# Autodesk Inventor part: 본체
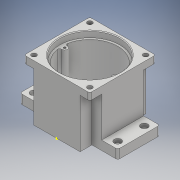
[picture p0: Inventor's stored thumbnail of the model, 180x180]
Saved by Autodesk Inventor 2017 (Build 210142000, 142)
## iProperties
Part Number: 본체
Material: 일반
Document SubType Name: Modeling
Designer: user
Density: 1 g/cm^3
Appearance: 기본값
Mass: 324.574 g
Surface Area: 793.93 cm^2
Volume: 324.574 cm^3
Author: user
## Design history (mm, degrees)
sketch "스케치1"
  geometry: L1 (-33, -47)-(33, -47); L2 (33, -47)-(33, 47); L3 (33, 47)-(-33, 47); L4 (-33, 47)-(-33, -47); L5 (-33, -47)-(33, 47); L6 (33, -47)-(-33, 47); L7 (-70, -30)-(70, -30); L8 (70, -30)-(70, 30); L9 (70, 30)-(-70, 30); L10 (-70, 30)-(-70, -30); L11 (-70, -30)-(70, 30); L12 (70, -30)-(-70, 30); 3 further points
  constraints: 24 end point, 5 midpoint, 4 parallel, 2 horizontal, 2 perpendicular, 1 coincident
  dimensions: "d3" = 60 distance of L7.end L8.end; "d4" = 66 distance of L2.end L3.end; "d5" = 37 distance between parallel lines of L10 L4; "d6" = 94 distance between parallel lines of L1 L3
extrude "돌출1" new body sketch "스케치1" distance "d7" = 13; taper "d8" = 0 deg
sketch "스케치2"
  geometry: L1 (33, -47)-(33, -30); L2 (33, -30)-(47, -30); L3 (47, -30)-(47, 30); L4 (47, 30)-(33, 30); L5 (33, 30)-(33, 47); L6 (33, 47)-(-33, 47); L7 (-33, 47)-(-33, 30); L8 (-33, 30)-(-47, 30); L9 (-47, 30)-(-47, -30); L10 (-47, -30)-(-33, -30); L11 (-33, -30)-(-33, -47); L12 (-33, -47)-(33, -47); 4 further points
  constraints: 24 end point, 8 perpendicular, 4 point on line, 3 coincident, 1 horizontal, 1 vertical
  dimensions: "d17" = 66 distance of L11.end L1.start; "d18" = 66 distance of L5.end L6.end; "d19" = 14 distance of L9.end L10.end; "d20" = 14 distance of L1.end L2.end; "d21" = 60 distance of L8.end L9.end; "d22" = 60 distance of L2.end L3.end
extrude "돌출2" join sketch "스케치2" distance "d11" = 57; taper "d12" = 0 deg
sketch "스케치4"
  geometry: L1 (47, 47)-(-47, 47); L2 (-47, 47)-(-47, -47); L3 (-47, -47)-(47, -47); L4 (47, -47)-(47, 47); L5 (47, 47)-(-47, -47); L6 (-47, 47)-(47, -47); 1 further point
  constraints: 12 end point, 2 midpoint, 2 parallel, 1 horizontal, 1 perpendicular
  dimensions: "d25" = 94 distance of L3.end L2.end; "d26" = 94 distance of L2.end L1.end
extrude "돌출4" join sketch "스케치4" distance "d27" = 10; taper "d28" = 0 deg
sketch "스케치5"
  geometry: C1 r 43 at (0, 0); 1 further point
  constraints: 1 centre point, 1 coincident
  dimensions: "d29" = 86 diameter of C1
extrude "돌출5" cut sketch "스케치5" distance "d30" = 9; taper "d31" = 0 deg
sketch "스케치6"
  geometry: C1 r 40 at (0, 0); 1 further point
  constraints: 1 centre point, 1 coincident
  dimensions: "d32" = 80 diameter of C1
sketch "스케치7"
  geometry: 1 further point
extrude "돌출6" cut sketch "스케치6" distance "d33" = 62; taper "d34" = 0 deg
sketch "스케치8"
  geometry: C1 r 21 at (0, 11); C2 r 15 at (0, -20); 1 further point
  constraints: 2 centre point, 2 vertical alignment
  dimensions: "d35" = 42 diameter of C1; "d36" = 30 diameter of C2; "d38" = 11 distance of point (0, 0) C1.centre; "d39" = 20 distance of C2.centre point (0, 0)
extrude "돌출7" join sketch "스케치8" distance "d40" = 7; taper "d41" = 0 deg
sketch "스케치9"
  geometry: C1 r 17.5 at (0, 11); 1 further point
  constraints: 1 centre point, 1 vertical alignment
  dimensions: "d42" = 35 diameter of C1; "d43" = 11 distance of point (0, 0) C1.centre
extrude "돌출8" cut sketch "스케치9" distance "d44" = 10; taper "d45" = 0 deg
sketch "스케치10"
  geometry: C1 r 12.5 at (0, 0); 1 further point
  constraints: 1 centre point, 1 vertical alignment
  dimensions: "d46" = 25 diameter of C1; "d47" = 11 distance of point (0, -11) C1.centre
extrude "돌출9" cut sketch "스케치10" distance "d48" = 4.7; taper "d49" = 0 deg
sketch "스케치11"
  geometry: C1 r 16 at (0, 0); 1 further point
  constraints: 1 centre point, 1 vertical alignment
  dimensions: "d50" = 32 diameter of C1; "d51" = 11 distance of point (0, -11) C1.centre
extrude "돌출10" cut sketch "스케치11" distance "d52" = 8.3; taper "d53" = 0 deg
sketch "스케치12"
  geometry: C1 r 16 at (0, 11) reference; C2 r 27.5 at (0, 11); 1 further point
  constraints: 1 centre point, 1 coincident
  dimensions: "d54" = 55 diameter of C2
extrude "돌출11" join sketch "스케치12" distance "d55" = 7; taper "d56" = 0 deg
sketch "스케치13"
  geometry: C1 r 11 at (0, -20); 1 further point
  constraints: 1 centre point, 1 vertical alignment
  dimensions: "d57" = 22 diameter of C1; "d58" = 20 distance of point (0, 0) C1.centre
extrude "돌출12" cut sketch "스케치13" distance "d59" = 7; taper "d60" = 0 deg
sketch "스케치14"
  geometry: C1 r 9.5 at (0, 0); 1 further point
  constraints: 1 centre point, 1 vertical alignment
  dimensions: "d61" = 19 diameter of C1; "d62" = 20 distance of point (0, 20) C1.centre
extrude "돌출13" cut sketch "스케치14" distance "d63" = 3; taper "d64" = 0 deg
sketch "스케치15"
  geometry: L1 (-70, -30)-(-70, 30) reference; L2 (-70, 30)-(-33, 30) reference; C1 r 2.25 at (-60, 18); 1 further point
  constraints: 1 centre point
  dimensions: "d65" = 4.5 diameter of C1; "d66" = 10 distance from line of L1 C1.centre; "d67" = 12 distance from line of L2 C1.centre
extrude "돌출14" cut sketch "스케치15" distance "d68" = 20; taper "d69" = 0 deg
sketch "스케치16"
  geometry: C1 r 2.25 at (60, 18) reference; C2 r 5 at (60, 18); 1 further point
  constraints: 1 centre point, 1 coincident
  dimensions: "d70" = 10 diameter of C2
extrude "돌출15" cut sketch "스케치16" distance "d71" = 5; taper "d72" = 0 deg
sketch "스케치17"
  geometry: L1 (-47, 47)-(-47, -47) reference; L2 (47, 47)-(-47, 47) reference; C1 r 3.5 at (-40, 40); 1 further point
  constraints: 1 centre point
  dimensions: "d79" = 7 diameter of C1; "d80" = 7 distance from line of L1 C1.centre; "d81" = 7 distance from line of L2 C1.centre
extrude "돌출16" cut sketch "스케치17" distance "d82" = 20; taper "d83" = 0 deg
sketch "스케치18"
  geometry: C1 r 4 at (-36, 0); 1 further point
  constraints: 1 centre point, 1 horizontal alignment
  dimensions: "d91" = 8 diameter of C1; "d92" = 36 distance of point (0, 0) C1.centre
extrude "돌출17" join sketch "스케치18" stored distance "d93" = 20; taper "d94" = 0 deg
fillet "모깎기1" dims "d95" = 3
fillet "모깎기2" dims "d96" = 3
sketch "스케치19"
  geometry: A1 r 4 centre (36, 0) between (36.19, 3.995) and (36.19, -3.995); A2 r 3 centre (36.333, -6.992) between (39.279, -7.559) and (36.19, -3.995); A3 r 3 centre (36.333, 6.992) between (36.19, 3.995) and (39.279, 7.559); A4 r 40 centre (0, 0) between (-39.279, -7.559) and (-39.279, 7.559) reference; 1 further point
  constraints: 8 point on circle, 4 tangent, 3 centre point, 1 horizontal alignment
  dimensions: "d97" = 8 diameter of A1; "d98" = 36 distance of A1.centre point (0, 0); "d101" = 6 diameter of A2; "d102" = 6 diameter of A3
extrude "돌출18" join sketch "스케치19" stored distance "d99" = 20; taper "d100" = 0 deg
sketch "스케치20"
  geometry: 2 further points
  constraints: 1 horizontal alignment
  dimensions: "d103" = 36 distance of point (36, 0) point (0, 0)
hole "구멍1" sketch "스케치20" at (36, 0) diameter "d104" = 3.242; stored, may be unused: countersink angle "d108" = 90 deg, drill point angle "d110" = 118 deg; dims "d105" = 7, "d106" = 4, "d107" = 2, "d109" = 9
chamfer "모따기1" distance "d111" = 1; stored, may be unused: second distance "d112" = 2, angle "d113" = 45 deg
chamfer "모따기2" distance "d114" = 1; stored, may be unused: second distance "d115" = 2, angle "d116" = 45 deg
chamfer "모따기3" distance "d117" = 0.8; stored, may be unused: second distance "d118" = 2, angle "d119" = 30 deg
fillet "모깎기3" dims "d120" = 3
sketch "스케치21" dims "d3" = 60, "d4" = 66, "d5" = 37, "d6" = 94
  geometry: L1 (66, 0)-(0, 0) reference; L2 (77, -80)-(-11, -80) reference; 4 further points
  constraints: 2 midpoint, 1 coincident, 1 vertical alignment, 1 other
  dimensions: "d121" = 40 distance from line of point (33, -40) L2
feature "엠보싱1" sketch "스케치21" dims "d3" = 60, "d4" = 66, "d5" = 37, "d6" = 94, "d17" = 66, "d18" = 66, "d19" = 14, "d20" = 14, "d21" = 60, "d22" = 60, "d122" = 0.5, "d123" = 0
fillet "모깎기4" dims "d124" = 3
node "솔리드1"
pattern_linear "직사각형 패턴1" dims "d75" = 120, "d78" = 38
pattern_linear "직사각형 패턴2" dims "d86" = 80, "d89" = 80
mirror "미러1"
